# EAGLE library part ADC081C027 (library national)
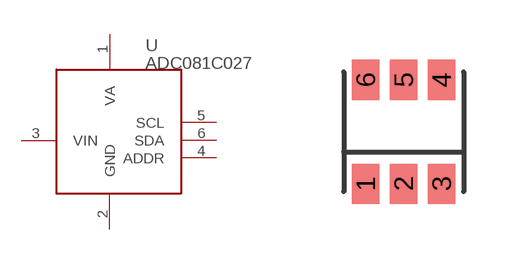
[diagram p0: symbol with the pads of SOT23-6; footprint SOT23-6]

Designator prefix U

## ADC081C027  [SOT23-6]
1  VA
2  GND
3  VIN
4  ADDR
5  SCL
6  SDA

## Footprint SOT23-6 (pad centres in mm)
smd 0.69 x 1: 1 -0.95,-1.3; 2 0,-1.3; 3 0.95,-1.3; 4 0.95,1.3; 5 0,1.3; 6 -0.95,1.3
